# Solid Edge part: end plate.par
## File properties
Author: Binay
Template: sync ansi part.par
Last saved by: CADCIM
Revision: 19
Application: Solid Edge
Accuracy: 0.990
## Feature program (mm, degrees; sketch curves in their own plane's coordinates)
sketch for "unnamed Hole 1" plane through (74.0576, 73.9259, 6.35) normal (0, 0, 1) x-axis (1, 0, 0)
  hole centre (-38.8262, -36.609) bore radius 3.302
hole "unnamed Hole 1" through
pattern "unnamed Pattern 1" of "unnamed Hole 1"
hole "unnamed Hole 2" through
hole "unnamed Hole 3" through
hole "unnamed Hole 4" through
pattern "PatternOccurrence_5"  XCount = 4; XOffset = 90 deg
pattern "unnamed Pattern 3" of "unnamed Hole 1"
pattern "PatternOccurrence_1"  XCount = 2; YCount = 2; XOffset = 76.2 mm; YOffset = 76.2 mm
hole "unnamed Hole 5" through
hole "unnamed Hole 6" through
hole "unnamed Hole 7" through
sketch for "Hole_5" plane through (73.6248, 74.4917, 6.35) normal (0, 0, 1) x-axis (1, 0, 0)
  hole centre (-0.2934, 0.9253) bore radius 12.7
hole "Hole_5" diameter 25.4 through
pattern "unnamed Pattern 4" of "Hole_5"
sketch for "Hole_6" plane through (74.8044, 76.257, 6.35) normal (0, 0, 1) x-axis (1, 0, 0)
  hole centre (-1.4729, 19.7975) bore radius 2.413
hole "Hole_6" diameter 4.826 through
pattern "unnamed Pattern 2" of "Hole_6"
pattern "unnamed Pattern 5" of "Hole_6"
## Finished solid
Body 1: solid body, 15 faces, 30 edges, 8 vertices.
  Faces by surface: cylinder 9, plane 6
  Edges by curve: circle 18, line 12
Bounding box of the edges (mm): 101.600 x 101.600 x 12.700, from (22.5315, 24.617, -6.35) to (124.1315, 126.217, 6.35).
Cylindrical faces by radius (mm): R2.413 x4, R3.302 x4, R12.7 x1
Planar faces by outward normal: +x 1, +y 1, +z 1, -x 1, -y 1, -z 1
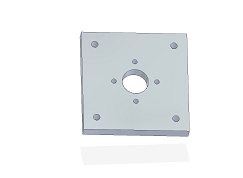
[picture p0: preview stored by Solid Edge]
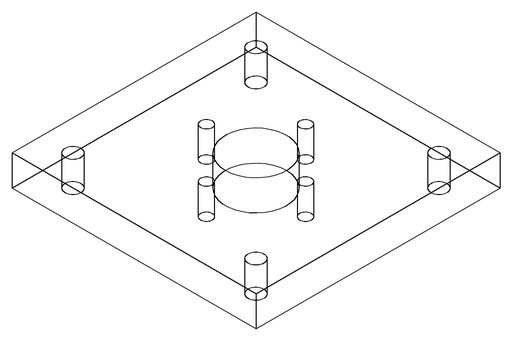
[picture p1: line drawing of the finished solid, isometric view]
